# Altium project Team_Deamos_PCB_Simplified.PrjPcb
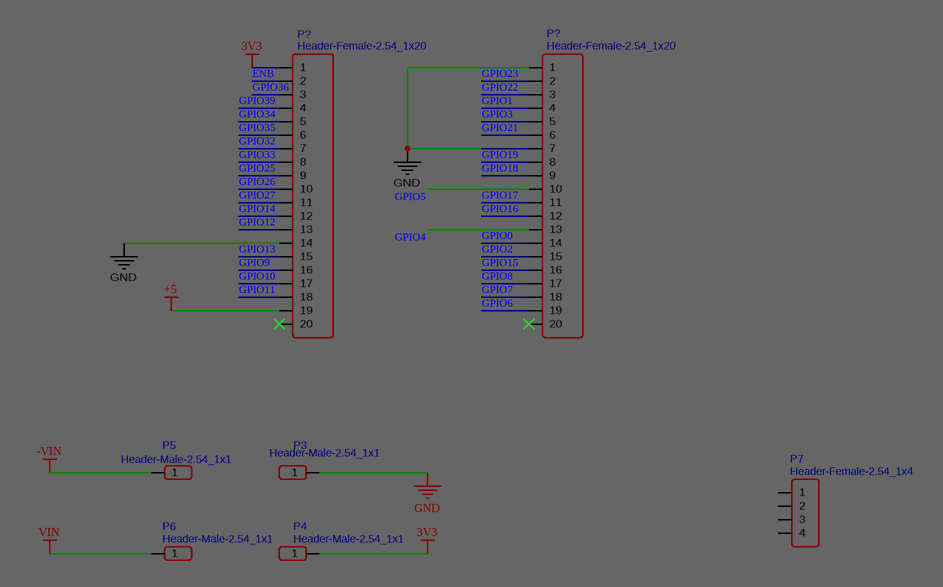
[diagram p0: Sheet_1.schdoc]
3 sheets, 32 parts. Net scope: global (net labels, ports and power ports of the same name join across sheets).
Board file: PCB1.PcbDoc
Sheets:
  Sheet_1.schdoc
  CAN.SchDoc
  Sheet1.SchDoc

## Sheet Sheet_1.schdoc
size 288 x 204 mm; SheetNumber: 1; SheetTotal: 2

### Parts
(Parts that share a designator on the sheet are numbered #1, #2 ... from top to bottom, then left to right.)
P3  Header-Male-2.54_1x1  [HDR-TH_1P-P2.54-V-M]
P4#1  Header-Male-2.54_1x1  [HDR-TH_1P-P2.54-V-M]
P5#1  Header-Male-2.54_1x1  [HDR-TH_1P-P2.54-V-M]
P6  Header-Male-2.54_1x1  [HDR-TH_1P-P2.54-V-M]
P7  Header-Female-2.54_1x4  [HDR-4X1/2.54]
P?#1  Header-Female-2.54_1x20  [AMPHENOL_76341-322LF]
P?#2  Header-Female-2.54_1x20  [HDR-TH_20P-P2.54-V-F]

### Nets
3V3: P4#1.1 P?#1.1
+5: P?#1.19
-VIN: P5#1.1
GND: P3.1 P?#1.14 P?#2.1 P?#2.7
VIN: P6.1
ENB: P?#1.2
GPIO0: P?#2.14
GPIO1: P?#2.4
GPIO2: P?#2.15
GPIO3: P?#2.5
GPIO4: P?#2.13
GPIO5: P?#2.10
GPIO6: P?#2.19
GPIO7: P?#2.18
GPIO8: P?#2.17
GPIO9: P?#1.16
GPIO10: P?#1.17
GPIO11: P?#1.18
GPIO12: P?#1.13
GPIO13: P?#1.15
GPIO14: P?#1.12
GPIO15: P?#2.16
GPIO16: P?#2.12
GPIO17: P?#2.11
GPIO18: P?#2.9
GPIO19: P?#2.8
GPIO21: P?#2.6
GPIO22: P?#2.3
GPIO23: P?#2.2
GPIO25: P?#1.9
GPIO26: P?#1.10
GPIO27: P?#1.11
GPIO32: P?#1.7
GPIO33: P?#1.8
GPIO34: P?#1.5
GPIO35: P?#1.6
GPIO36: P?#1.3
GPIO39: P?#1.4

Not connected (* = marked no-connect by the designer): P7 1 2 3 4; P?#1 20*; P?#2 20*

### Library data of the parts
P3 P4#1 P5#1 P6 = Header-Male-2.54_1x1: Manufacturer: BOOMELE(博穆精密); Manufacturer Part: 2.54-1*1P针
P7 = Header-Female-2.54_1x4: Manufacturer: ReliaPro
P?#1 P?#2 = Header-Female-2.54_1x20: Manufacturer: BOOMELE(博穆精密); Manufacturer Part: 2.54-1*20P母

## Sheet CAN.SchDoc
size A4; SheetNumber: 2; SheetTotal: 2
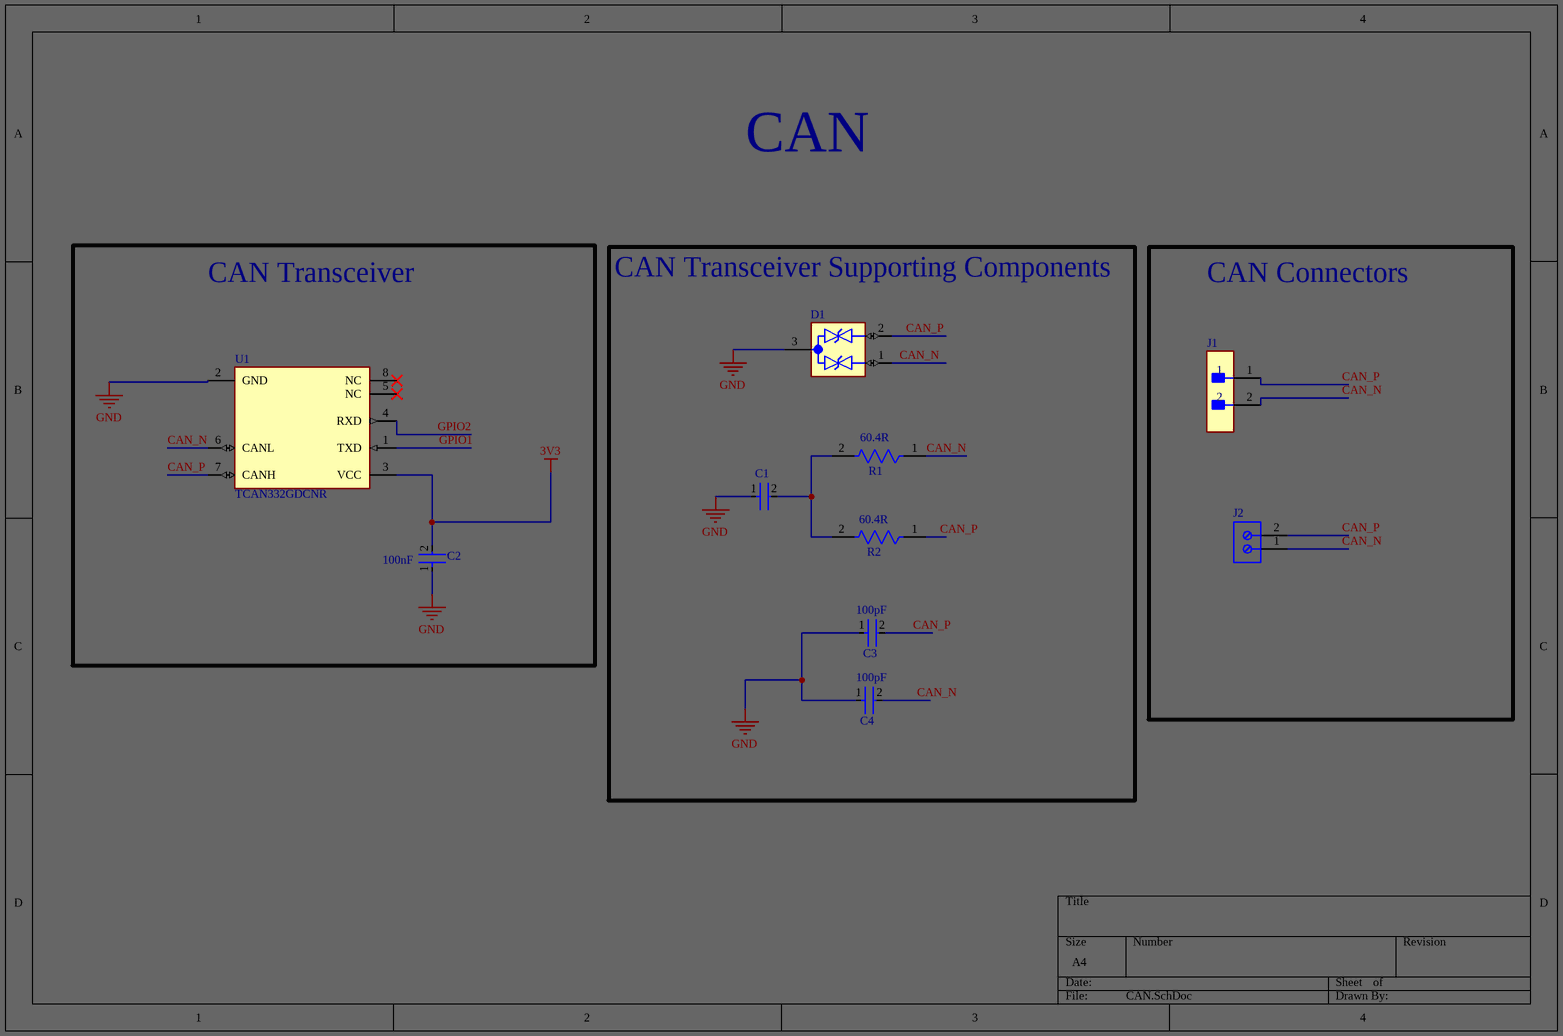
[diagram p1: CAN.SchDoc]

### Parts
C1  CC0402KRX7R6BB472  [FP-CC0402-MFG]  (value not drawn)
C2  Capacitance: 100nF  [FP-CL17-IPC_C]  (hidden comment: CL05B104KP5NNNC)
C3  value 100pF  [FP-CL05-MFG]  (hidden comment: CL05C101JB5NNNC)
C4  value 100pF  [FP-CL05-MFG]  (hidden comment: CL05C101JB5NNNC)
D1  ESD2CAN24DBZRQ1  [SOT95P237X112-3N]  (value not drawn)
J1  M20-9990246  [FP-M20-9990246-MFG]  (value not drawn)
J2  691137710002  [691137710002]  (value not drawn)
R1  Resistance: 60.4R  [FP-ERJ2RK-IPC_A]  (hidden comment: ERJ-2RKF60R4X)
R2  Resistance: 60.4R  [FP-ERJ2RK-IPC_A]  (hidden comment: ERJ-2RKF60R4X)
U1  TCAN332GDCNR  [FP-DCN0008A-IPC_A]

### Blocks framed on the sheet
CAN Transceiver: C2 U1
CAN Transceiver Supporting Components: C1 C3 C4 D1 R1 R2
CAN Connectors: J1 J2

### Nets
3V3: C2.2 U1.3(VCC)
GND: C1.1 C2.1 C3.1 C4.1 D1.3(GND) U1.2(GND)
CAN_N: C4.2 D1.1(IO1) J1.2 J2.1 R1.1 U1.6(CANL)
CAN_P: C3.2 D1.2(IO2) J1.1 J2.2 R2.1 U1.7(CANH)
GPIO1: U1.1(TXD)
GPIO2: U1.4(RXD)
NetC1_2: C1.2 R1.2 R2.2

Not connected (* = marked no-connect by the designer): U1 5(NC)* 8(NC)*

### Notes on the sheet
- CAN

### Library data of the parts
C1 = CMP-03422-001343-1: CC0402 4.7 nF X7R 10.00% 10 V; Manufacturer: YAGEO; Tolerance: 0.1; Material: Ceramic; Temperature Coefficient: 30ppm/°C; Value: 4.7 nF; Automotive Grade: NA; Voltage Rating: 10 V
C2 = CMP-13271-001069-1: Cap Ceramic 100nF 10V X7R ±10% SMD 0402 +125°C Paper T/R
C3 C4 = CMP-13271-000010-1: CAP CER 100PF 50V C0G/NP0 0402; Manufacturer: Samsung; Tolerance: 5%; Temperature Characteristic: C0G; Material: Ceramic; Temperature Coefficient: 30ppm/°C
D1 = ESD2CAN24DBZRQ1: Automotive, dual, 3-pF, ±24-V, ±30-kV ESD protection diode for CAN and in-vehicle networks 3-SOT-23 -55 to 150; Manufacturer: Texas Instruments
J1 = CMP-15831-000009-1: CONN HEADER VERT 2POS 2.54MM; Manufacturer: Harwin; Conn Gender: Male; Conn Orientation: Vertical; Number Of Contacts: 2; Current Rating: 3A
J2 = CMP-1502-03324-2: NexarPartId: 78871135; Voltage Rating: 300V; Number of Contacts: 2; Current Rating: 16A
R1 R2 = CMP-2002-01013-2: RES SMD 60.4 OHM 1% 1/10W 0402; Voltage Rating (DC): 50V; Temperature Coefficient: 100ppm/°C; Max Power Dissipation: 100mW
U1 = CMP-04872-000119-1: IC TRANSCEIVER 1/1 SOT23-8; Receiver Hysteresis: 120mV; Data Rate: 5Mbps

## Sheet Sheet1.SchDoc
size A4; SheetNumber: 3; SheetTotal: 3
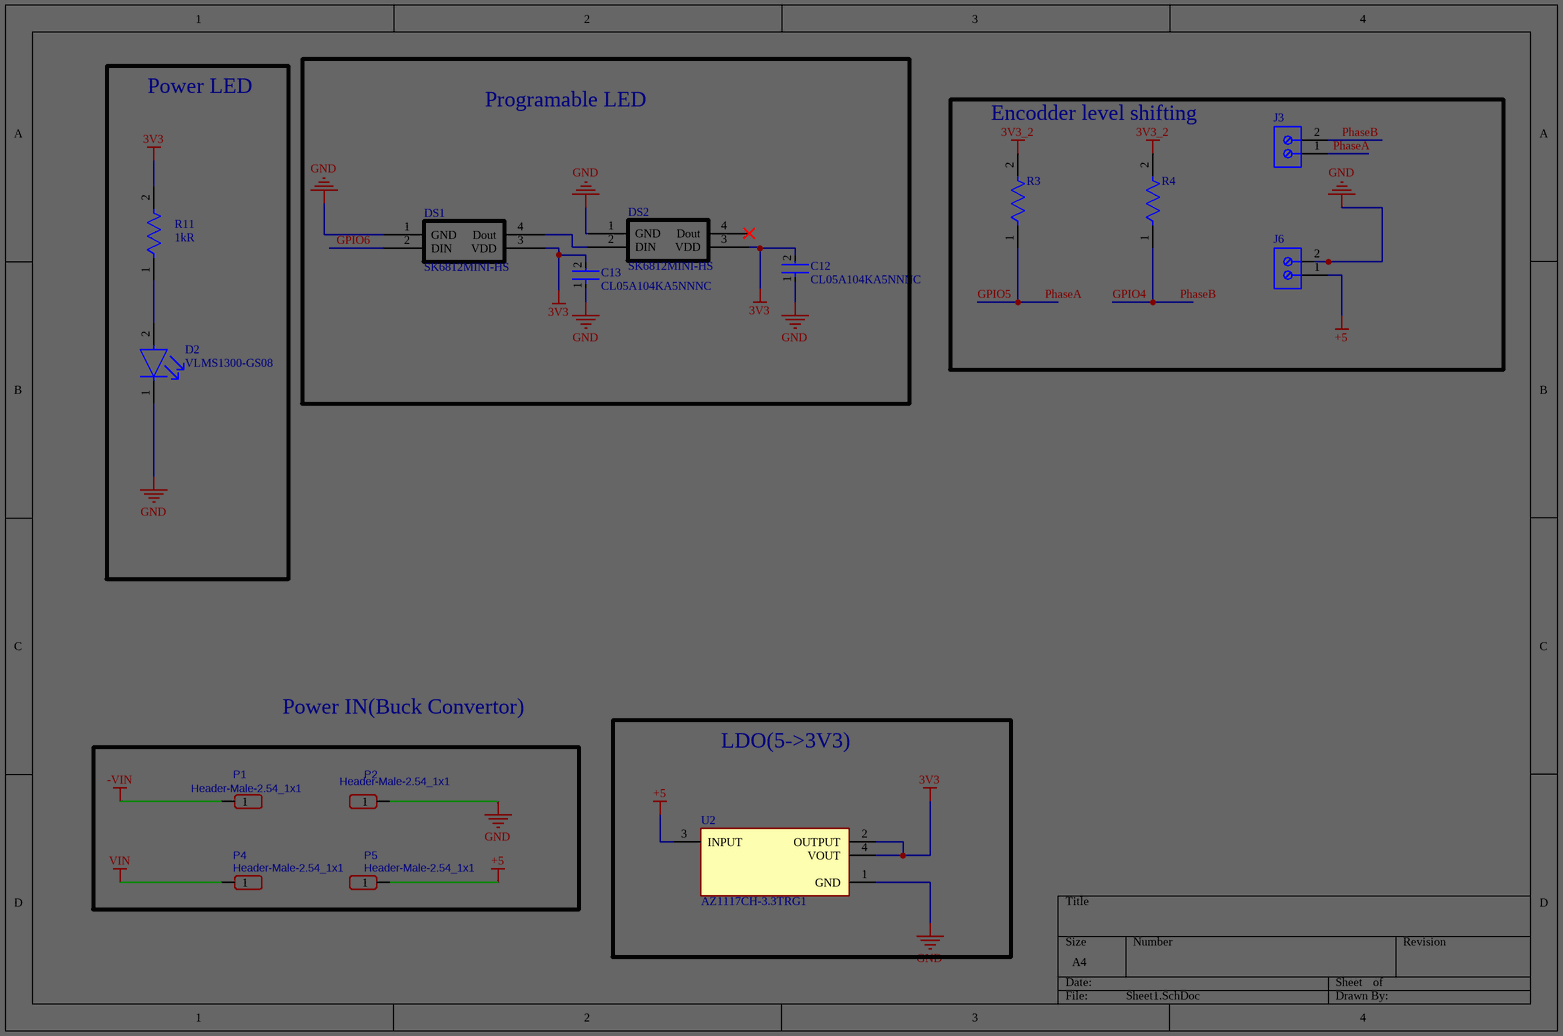
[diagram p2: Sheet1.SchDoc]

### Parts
(Parts that share a designator on the sheet are numbered #1, #2 ... from top to bottom, then left to right.)
C12  CL05A104KA5NNNC  [FP-CL278-IPC_C]
C13  CL05A104KA5NNNC  [FP-CL278-IPC_C]
D2  VLMS1300-GS08  [FP-6_541-5092_01-4-MFG]
DS1  SK6812MINI-HS  [LED]
DS2  SK6812MINI-HS  [LED]
J3  691137710002  [691137710002]  (value not drawn)
J6  691137710002  [691137710002]  (value not drawn)
P1  Header-Male-2.54_1x1  [PCBComponent_1]
P2  Header-Male-2.54_1x1  [PCBComponent_1]
P4#2  Header-Male-2.54_1x1  [PCBComponent_1]
P5#2  Header-Male-2.54_1x1  [PCBComponent_1]
R3  RC0402JR-074K7L  [FP-RC0402-0_4-MFG]  (value not drawn)
R4  RC0402JR-074K7L  [FP-RC0402-0_4-MFG]  (value not drawn)
R11  Resistance: 1kR  [FP-CRCW0603-e3-MFG]  (hidden comment: CRCW06031K00FKEA)
U2  AZ1117CH-3.3TRG1  [FP-SOT223-MFG]

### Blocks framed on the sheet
Power LED: D2 R11
Programable LED: C12 C13 DS1 DS2
Encodder level shifting: J3 J6 R3 R4
LDO(5->3V3): U2

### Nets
3V3: C12.2 C13.2 DS1.3(VDD) DS2.3(VDD) R11.2 U2.2(OUTPUT) U2.4(VOUT)
3V3_2: R3.2 R4.2
+5: J6.1 P5#2.1 U2.3(INPUT)
-VIN: P1.1
GND: C12.1 C13.1 D2.1(C) DS1.1(GND) DS2.1(GND) J6.2 P2.1 U2.1(GND)
VIN: P4#2.1
GPIO4: J3.2 R4.1  [also labelled PhaseB]
GPIO5: J3.1 R3.1  [also labelled PhaseA]
GPIO6: DS1.2(DIN)
NetD2_2: D2.2(A) R11.1
NetDS1_4: DS1.4(Dout) DS2.2(DIN)

Not connected (* = marked no-connect by the designer): DS2 4(Dout)*

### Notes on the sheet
- Power IN(Buck Convertor)

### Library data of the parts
C12 C13 = CMP-13271-000728-1: Cap Ceramic 100nF 25V X5R ±10% SMD 0402 +85°C Paper T/R
D2 = CMP-02520-000012-1: LED RED 0603 SMD; Manufacturer: Vishay; Forward Voltage: 2V; Reverse Voltage: 5V; Power Dissipation: 75mW; Forward Current: 20mA; Luminous Intensity: 54mcd; Led Orientation: Top View; Peak Emmision Wavelength: 639nm; Viewing Angle: 130°; Wavelength: 631nm
J3 J6 = CMP-1502-03324-2: as J2 on sheet CAN
P1 P2 P4#2 P5#2 = Header-Male-2.54_1x1: as P3 on sheet Sheet_1
R3 R4 = CMP-2002-08011-2: Tolerance: 5%; Power Rating: 63mW; Resistance: 4.7kΩ; Voltage Rating: 50V; Temperature Coefficient: 100ppm/°C
R11 = CMP-1666-00003-5: RES Thick Film, 1kΩ, 1%, 0.1W, 100ppm/°C, 0603; Max Power Dissipation: 100mW; Voltage Rating: 75V; Value: 1kR
U2 = CMP-12756-000028-1: IC REG LINEAR 3.3V 800MA SOT223; Accuracy: 1%; Reference Voltage: 1.262V; Quiescent Current: 6mA; Power Supply Rejection Ratio (PSRR): 70dB; Max Input Voltage: 15V; Max Output Current: 1.35A; Output Type: Fixed; Min Current Limit: 1A; Number of Regulators: 1; Polarity: Positive; Dropout Voltage: 1.2V

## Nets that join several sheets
3V3: Sheet_1 (P4#1.1 P?#1.1), CAN (C2.2 U1.3), Sheet1 (7 pins)
+5: Sheet_1 (P?#1.19), Sheet1 (J6.1 P5#2.1 U2.3)
-VIN: Sheet_1 (P5#1.1), Sheet1 (P1.1)
GND: Sheet_1 (P3.1 P?#1.14 P?#2.1 P?#2.7), CAN (6 pins), Sheet1 (8 pins)
VIN: Sheet_1 (P6.1), Sheet1 (P4#2.1)
GPIO1: Sheet_1 (P?#2.4), CAN (U1.1)
GPIO2: Sheet_1 (P?#2.15), CAN (U1.4)
GPIO4: Sheet_1 (P?#2.13), Sheet1 (J3.2 R4.1)
GPIO5: Sheet_1 (P?#2.10), Sheet1 (J3.1 R3.1)
GPIO6: Sheet_1 (P?#2.19), Sheet1 (DS1.2)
